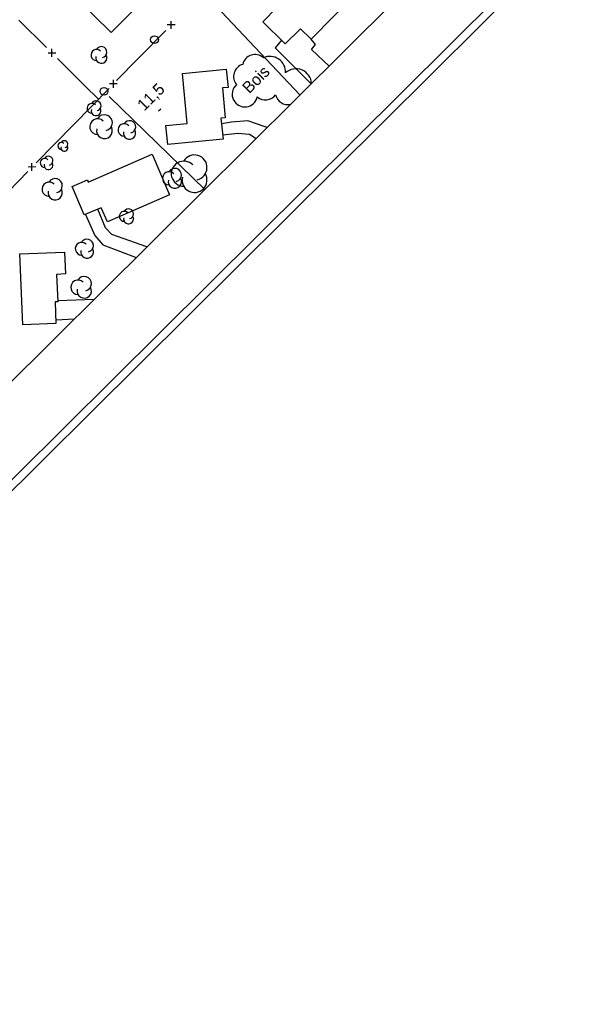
# Model space of a CAD drawing. Extents: x 381879 to 384696, y 5564785 to 5567594.
# Drawn here: x 383625.9 to 383774.2, y 5565489.3 to 5565742.9 of the extents above; entities that cross this region are included whole.
import ezdxf

# ---------------------------------------------------------------- set-up
doc = ezdxf.new("R2010")
doc.units = 0
for name, color, linetype in [('Niveau 19', 7, 'Continuous'), ('Niveau 3', 7, 'Continuous'), ('Niveau 31', 7, 'Continuous'), ('Niveau 36', 7, 'Continuous'), ('Niveau 37', 7, 'Continuous'), ('Niveau 41', 7, 'Continuous'), ('Niveau 44', 7, 'Continuous'), ('Niveau 60', 7, 'Continuous')]:
    doc.layers.add(name, color=color, linetype=linetype)

msp = doc.modelspace()

# ---------------------------------------------------------------- linework, layer by layer
at = {"layer": 'Niveau 19'}
for points in [[(383705.58, 5565731.01), (383701.05, 5565735.26), (383702.06, 5565736.59), (383701, 5565737.9)], [(383693.31, 5565737.67), (383691.69, 5565735.73), (383698.75, 5565728.66), (383700.96, 5565726.43)], [(383689.63, 5565715.19), (383688.88, 5565715.49), (383684.63, 5565716.88), (383680.42, 5565716.58), (383677.86, 5565716.16)], [(383678.18, 5565713.29), (383682.06, 5565713.71), (383685.08, 5565713.47), (383686.79, 5565712.36)], [(383642.82, 5565692.83), (383645.27, 5565687.42), (383647.32, 5565685), (383651.84, 5565683.3), (383655.89, 5565681.71)], [(383658.64, 5565684.44), (383649.57, 5565687.65), (383648.01, 5565689.36), (383646.04, 5565694.16)], [(383645.02, 5565670.93), (383635.66, 5565670.58)], [(383635.18, 5565665.72), (383639.99, 5565665.94)]]:
    msp.add_lwpolyline(points, dxfattribs=at)
at = {"layer": 'Niveau 3'}
msp.add_line((383661.66, 5565719.45), (383662.23, 5565720.02), dxfattribs=at)
at = {"layer": 'Niveau 31'}
for points in [[(383660.8, 5565751.12), (383649.43, 5565739.65), (383640.54, 5565748.45), (383642.71, 5565750.65), (383641.71, 5565751.64), (383648.6, 5565758.6), (383649.61, 5565757.59), (383651.91, 5565759.91)], [(383694.3, 5565736.7), (383688.5, 5565742.4), (383692.1, 5565746.1), (383692.6, 5565745.6), (383704.5, 5565757.8), (383712.7, 5565749.9), (383701, 5565737.9), (383698.2, 5565740.6)], [(383664, 5565710.8), (383663.5, 5565715.7), (383669, 5565716.2), (383667.8, 5565729.1), (383679.1, 5565730.2), (383679.6, 5565725.5), (383678.1, 5565725.4), (383678.8, 5565717.7), (383677.7, 5565717.6), (383678.3, 5565712.2)], [(383664.5, 5565697.9), (383648.48, 5565690.94), (383646.88, 5565694.51), (383642.5, 5565692.7), (383639.4, 5565700), (383643.3, 5565701.7), (383643.5, 5565701.1), (383660, 5565708.3)], [(383626.67, 5565664.37), (383625.89, 5565682.65), (383637.43, 5565683.14), (383637.67, 5565677.49), (383635.37, 5565677.39), (383635.67, 5565670.33), (383634.99, 5565670.3), (383635.22, 5565664.73)]]:
    msp.add_lwpolyline(points, close=True, dxfattribs=at)
at = {"layer": 'Niveau 36'}
for centre in [(383660.59, 5565737.8), (383647.59, 5565724.5)]:
    msp.add_circle(centre, 1, dxfattribs=at)
at = {"layer": 'Niveau 37'}
for p, q in [((383665.91, 5565741.6), (383663.9, 5565741.58)), ((383664.91, 5565740.59), (383664.9, 5565742.59)), ((383634.19, 5565733.4), (383634.18, 5565735.4)), ((383633.18, 5565734.4), (383635.18, 5565734.4)), ((383651.01, 5565726.44), (383649.01, 5565726.41)), ((383650.02, 5565725.42), (383650, 5565727.43)), ((383630.01, 5565705.05), (383628.01, 5565705.02)), ((383629.02, 5565704.03), (383629, 5565706.04))]:
    msp.add_line(p, q, dxfattribs=at)
for points in [[(383625.67, 5565742.86), (383632.76, 5565735.81)], [(383656.49, 5565733.03), (383663.5, 5565740.16)], [(383635.6, 5565732.99), (383642.69, 5565725.94)], [(383650.94, 5565727.38), (383650.85, 5565727.29), (383656.49, 5565733.03)], [(383639.71, 5565715.88), (383648.88, 5565725.27)], [(383642.69, 5565725.94), (383646.16, 5565722.49)], [(383630.14, 5565706.07), (383639.71, 5565715.88)], [(383622.96, 5565698.68), (383625.41, 5565701.24), (383627.94, 5565703.84)]]:
    msp.add_lwpolyline(points, dxfattribs=at)
at = {"layer": 'Niveau 41'}
for points in [[(383673.51, 5565749.72), (383698.07, 5565723.56)], [(383648.92, 5565723.19), (383673.57, 5565699.25)]]:
    msp.add_lwpolyline(points, dxfattribs=at)
at = {"layer": 'Niveau 44'}
for centre, radius, start, end in [((383645.68, 5565733.86), 1.43, 44.1153, 269.8039), ((383646.91, 5565734.58), 1.43, 282.2692, 149.7262), ((383646.91, 5565733.14), 1.43, 166.9368, 29.6212), ((383644.48, 5565720.13), 1.26, 44.1153, 269.8039), ((383645.56, 5565719.5), 1.26, 166.9368, 29.6212), ((383645.56, 5565720.77), 1.26, 282.2692, 149.7262), ((383647.71, 5565716.43), 2.04, 282.2692, 149.7262), ((383645.95, 5565715.41), 2.04, 44.1153, 269.8039), ((383647.71, 5565714.38), 2.04, 166.9368, 29.6212), ((383652.81, 5565714.55), 1.59, 44.1153, 269.8039), ((383654.17, 5565715.34), 1.59, 282.2692, 149.7262), ((383654.17, 5565713.75), 1.59, 166.9368, 29.6212), ((383636.62, 5565710.44), 0.895, 44.1153, 269.8039), ((383637.39, 5565709.99), 0.895, 166.9368, 29.6212), ((383637.39, 5565710.89), 0.895, 282.2692, 149.7262), ((383633.28, 5565706.64), 1.14, 282.2692, 149.7262), ((383670.91, 5565704.9), 3.22, 282.2692, 149.7262), ((383632.31, 5565706.07), 1.14, 44.1153, 269.8039), ((383633.28, 5565705.5), 1.14, 166.9368, 29.6212), ((383668.14, 5565703.3), 3.22, 44.1153, 269.8039), ((383664.38, 5565702.11), 1.71, 44.1153, 269.8039), ((383665.85, 5565702.97), 1.71, 282.2692, 149.7262), ((383670.91, 5565701.69), 3.22, 166.9368, 29.6212), ((383633.44, 5565699.3), 1.83, 44.1153, 269.8039), ((383635.02, 5565700.21), 1.83, 282.2692, 149.7262), ((383665.85, 5565701.26), 1.71, 166.9368, 29.6212), ((383635.02, 5565698.38), 1.83, 166.9368, 29.6212), ((383652.81, 5565692.33), 1.28, 44.1153, 269.8039), ((383653.92, 5565691.69), 1.28, 166.9368, 29.6212), ((383653.92, 5565692.98), 1.28, 282.2692, 149.7262), ((383641.83, 5565683.99), 1.64, 44.1153, 269.8039), ((383643.24, 5565684.81), 1.64, 282.2692, 149.7262), ((383643.24, 5565683.17), 1.64, 166.9368, 29.6212), ((383640.89, 5565674.07), 1.86, 44.1153, 269.8039), ((383642.49, 5565675), 1.86, 282.2692, 149.7262), ((383642.49, 5565673.14), 1.86, 166.9368, 29.6212)]:
    msp.add_arc(centre, radius, start, end, dxfattribs=at)
for centre, major_axis, ratio, start_param, end_param in [((383686.5, 5565730.7), (-1.79, 2.73), 0.992041, 4.975343, 7.049331), ((383690.34, 5565729.46), (-3.07, 2.63), 0.998665, 3.803957, 5.849037), ((383684.24, 5565728.31), (-0.67, -3.19), 0.999932, 3.633858, 5.610393), ((383697.04, 5565726.26), (-3.97, -0.78), 0.996768, 3.01596, 5.241204), ((383683.87, 5565723.77), (-0.07, -3.27), 0.999983, 3.872164, 5.220282), ((383683.9, 5565723.74), (-1.1, -3.07), 0.996814, 5.529034, 7.983421), ((383689.17, 5565725.54), (3.22, 0.49), 0.999575, 3.858498, 5.496198), ((383694.98, 5565724.34), (3.02, -1.25), 0.999385, 3.760774, 5.304528)]:
    msp.add_ellipse(centre, major_axis=major_axis, ratio=ratio, start_param=start_param, end_param=end_param, dxfattribs=at)
at = {"layer": 'Niveau 60'}
msp.add_lwpolyline([(382780.54, 5564785.16), (381879.11, 5565693.82), (383794.51, 5567593.97), (384695.95, 5566685.3), (382780.55, 5564785.15)], dxfattribs=at)
for points in [[(381881.93, 5565693.86), (383794.53, 5567591.15), (384693.12, 5566685.31), (382780.52, 5564788.02)], [(383653.8, 5566971.92), (383426.67, 5567200.87), (383197.47, 5566973.49), (381907.4, 5565693.71), (382780.65, 5564813.45), (384299.92, 5566320.61)]]:
    msp.add_lwpolyline(points, close=True, dxfattribs=at)

# ---------------------------------------------------------------- texts
at = {"layer": 'Niveau 3'}
msp.add_text('11,5 ', height=3, rotation=44.7717, dxfattribs=at).set_placement((383657.95, 5565719.26))
at = {"layer": 'Niveau 44'}
msp.add_text('Bois', height=3, rotation=44.7707, dxfattribs=at).set_placement((383685.02, 5565723.75))

doc.saveas('drawing.dxf')
